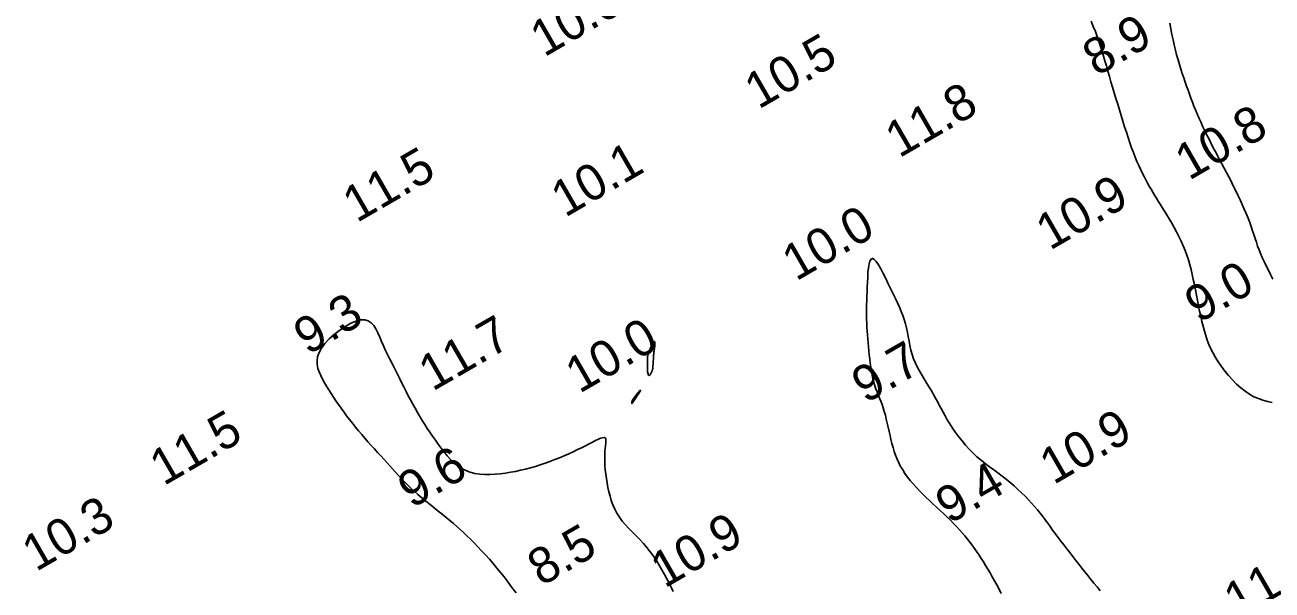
# Model space of a CAD drawing. Extents: x 3024098 to 3056816, y 418252 to 509144.
# Drawn here: x 3035988.1 to 3036161.3, y 419913.7 to 419992.1 of the extents above; entities that cross this region are included whole.
import ezdxf

# ---------------------------------------------------------------- set-up
doc = ezdxf.new("R2010")
doc.units = 0
doc.layers.add('V-CHAN-CONT-EL10', color=7, linetype='Continuous')
doc.layers.add('V-TOPO-SOUN-0911', color=7, linetype='Continuous')

msp = doc.modelspace()

# ---------------------------------------------------------------- linework, layer by layer
at = {"layer": 'V-CHAN-CONT-EL10'}
for points in [[(3036136.16, 419992.61), (3036136.46, 419991.89), (3036136.75, 419991.17), (3036137.01, 419990.48), (3036137.25, 419989.79), (3036137.47, 419989.12), (3036137.69, 419988.45), (3036137.89, 419987.77), (3036138.08, 419987.09), (3036138.28, 419986.4), (3036138.49, 419985.69), (3036138.7, 419984.95), (3036138.92, 419984.2), (3036139.14, 419983.44), (3036139.37, 419982.66), (3036139.61, 419981.87), (3036139.85, 419981.08), (3036140.09, 419980.29), (3036140.33, 419979.51), (3036140.57, 419978.73), (3036140.82, 419977.96), (3036141.06, 419977.2), (3036141.3, 419976.47), (3036141.55, 419975.75), (3036141.79, 419975.06), (3036142.03, 419974.4), (3036142.28, 419973.76), (3036142.52, 419973.16), (3036142.77, 419972.6), (3036143.02, 419972.06), (3036143.26, 419971.55), (3036143.51, 419971.06), (3036143.75, 419970.6), (3036144, 419970.15), (3036144.24, 419969.72), (3036144.48, 419969.3), (3036144.72, 419968.89), (3036144.97, 419968.48), (3036145.22, 419968.07), (3036145.48, 419967.65), (3036145.76, 419967.21), (3036146.04, 419966.74), (3036146.35, 419966.25), (3036146.67, 419965.73), (3036147, 419965.17), (3036147.35, 419964.59), (3036147.69, 419963.99), (3036148.03, 419963.37), (3036148.36, 419962.73), (3036148.67, 419962.09), (3036148.96, 419961.44), (3036149.22, 419960.79), (3036149.45, 419960.14), (3036149.67, 419959.48), (3036149.86, 419958.82), (3036150.04, 419958.14), (3036150.2, 419957.46), (3036150.35, 419956.76), (3036150.5, 419956.05), (3036150.65, 419955.33), (3036150.79, 419954.6), (3036150.93, 419953.85), (3036151.08, 419953.11), (3036151.23, 419952.38), (3036151.38, 419951.66), (3036151.54, 419950.95), (3036151.71, 419950.27), (3036151.89, 419949.61), (3036152.08, 419948.97), (3036152.29, 419948.35), (3036152.53, 419947.74), (3036152.79, 419947.14), (3036153.09, 419946.54), (3036153.43, 419945.93), (3036153.81, 419945.32), (3036154.25, 419944.69), (3036154.72, 419944.06), (3036155.23, 419943.43), (3036155.78, 419942.83), (3036156.35, 419942.25), (3036156.94, 419941.72), (3036157.55, 419941.25), (3036158.16, 419940.84), (3036158.78, 419940.5), (3036159.4, 419940.23), (3036160.03, 419940.02), (3036160.66, 419939.84), (3036161.3, 419939.7)], [(3036161.41, 419956.83), (3036161.09, 419957.47), (3036160.78, 419958.08), (3036160.48, 419958.67), (3036160.2, 419959.25), (3036159.94, 419959.8), (3036159.7, 419960.35), (3036159.48, 419960.88), (3036159.29, 419961.41), (3036159.11, 419961.93), (3036158.94, 419962.46), (3036158.77, 419963), (3036158.59, 419963.54), (3036158.4, 419964.1), (3036158.19, 419964.68), (3036157.96, 419965.28), (3036157.71, 419965.91), (3036157.44, 419966.54), (3036157.15, 419967.19), (3036156.85, 419967.84), (3036156.54, 419968.49), (3036156.22, 419969.14), (3036155.9, 419969.78), (3036155.59, 419970.41), (3036155.27, 419971.02), (3036154.95, 419971.62), (3036154.63, 419972.22), (3036154.32, 419972.81), (3036154.01, 419973.39), (3036153.7, 419973.98), (3036153.39, 419974.56), (3036153.08, 419975.15), (3036152.78, 419975.73), (3036152.49, 419976.32), (3036152.2, 419976.91), (3036151.92, 419977.49), (3036151.65, 419978.06), (3036151.39, 419978.63), (3036151.13, 419979.2), (3036150.9, 419979.75), (3036150.67, 419980.3), (3036150.45, 419980.84), (3036150.23, 419981.38), (3036150.03, 419981.92), (3036149.83, 419982.47), (3036149.62, 419983.03), (3036149.42, 419983.59), (3036149.22, 419984.17), (3036149.02, 419984.76), (3036148.81, 419985.36), (3036148.62, 419985.97), (3036148.42, 419986.61), (3036148.23, 419987.26), (3036148.04, 419987.93), (3036147.87, 419988.61), (3036147.7, 419989.32), (3036147.54, 419990.05), (3036147.39, 419990.79), (3036147.24, 419991.55), (3036147.09, 419992.33)], [(3036137.44, 419913.57), (3036136.99, 419914.09), (3036136.55, 419914.62), (3036136.12, 419915.14), (3036135.71, 419915.66), (3036135.29, 419916.19), (3036134.88, 419916.72), (3036134.47, 419917.25), (3036134.05, 419917.78), (3036133.63, 419918.32), (3036133.2, 419918.86), (3036132.78, 419919.4), (3036132.37, 419919.94), (3036131.96, 419920.46), (3036131.56, 419920.98), (3036131.18, 419921.49), (3036130.82, 419921.98), (3036130.47, 419922.46), (3036130.13, 419922.93), (3036129.79, 419923.39), (3036129.44, 419923.85), (3036129.08, 419924.31), (3036128.71, 419924.78), (3036128.32, 419925.24), (3036127.9, 419925.72), (3036127.46, 419926.2), (3036126.99, 419926.68), (3036126.5, 419927.16), (3036126, 419927.64), (3036125.47, 419928.11), (3036124.93, 419928.58), (3036124.37, 419929.03), (3036123.79, 419929.47), (3036123.21, 419929.91), (3036122.63, 419930.34), (3036122.04, 419930.77), (3036121.46, 419931.21), (3036120.88, 419931.67), (3036120.31, 419932.15), (3036119.76, 419932.66), (3036119.23, 419933.2), (3036118.71, 419933.77), (3036118.23, 419934.35), (3036117.76, 419934.95), (3036117.33, 419935.54), (3036116.92, 419936.14), (3036116.54, 419936.72), (3036116.19, 419937.29), (3036115.88, 419937.83), (3036115.59, 419938.35), (3036115.33, 419938.85), (3036115.07, 419939.34), (3036114.81, 419939.83), (3036114.56, 419940.31), (3036114.29, 419940.8), (3036114, 419941.3), (3036113.69, 419941.81), (3036113.36, 419942.34), (3036113.02, 419942.88), (3036112.68, 419943.43), (3036112.35, 419943.99), (3036112.04, 419944.57), (3036111.75, 419945.16), (3036111.5, 419945.75), (3036111.3, 419946.36), (3036111.13, 419946.97), (3036110.99, 419947.59), (3036110.87, 419948.21), (3036110.75, 419948.83), (3036110.64, 419949.43), (3036110.51, 419950.04), (3036110.37, 419950.63), (3036110.2, 419951.2), (3036110, 419951.77), (3036109.78, 419952.34), (3036109.53, 419952.92), (3036109.26, 419953.51), (3036108.97, 419954.12), (3036108.66, 419954.76), (3036108.33, 419955.44), (3036107.99, 419956.15), (3036107.64, 419956.88), (3036107.29, 419957.59), (3036106.94, 419958.24), (3036106.61, 419958.8), (3036106.3, 419959.26), (3036106.03, 419959.56), (3036105.79, 419959.68), (3036105.6, 419959.6), (3036105.44, 419959.33), (3036105.33, 419958.92), (3036105.24, 419958.39), (3036105.17, 419957.77), (3036105.13, 419957.1), (3036105.09, 419956.4), (3036105.06, 419955.72), (3036105.04, 419955.07), (3036105.02, 419954.45), (3036105, 419953.86), (3036104.98, 419953.3), (3036104.97, 419952.76), (3036104.96, 419952.23), (3036104.96, 419951.71), (3036104.97, 419951.19), (3036104.99, 419950.67), (3036105.02, 419950.14), (3036105.05, 419949.61), (3036105.09, 419949.07), (3036105.13, 419948.53), (3036105.18, 419947.98), (3036105.23, 419947.42), (3036105.29, 419946.86), (3036105.35, 419946.29), (3036105.41, 419945.72), (3036105.48, 419945.15), (3036105.56, 419944.59), (3036105.65, 419944.04), (3036105.75, 419943.5), (3036105.86, 419942.98), (3036105.98, 419942.49), (3036106.12, 419942.02), (3036106.28, 419941.58), (3036106.45, 419941.15), (3036106.62, 419940.72), (3036106.79, 419940.3), (3036106.96, 419939.86), (3036107.13, 419939.42), (3036107.29, 419938.95), (3036107.44, 419938.45), (3036107.58, 419937.92), (3036107.71, 419937.38), (3036107.84, 419936.82), (3036107.97, 419936.25), (3036108.1, 419935.68), (3036108.23, 419935.1), (3036108.36, 419934.54), (3036108.5, 419933.98), (3036108.66, 419933.43), (3036108.82, 419932.9), (3036109.01, 419932.37), (3036109.21, 419931.85), (3036109.45, 419931.34), (3036109.7, 419930.83), (3036109.99, 419930.33), (3036110.31, 419929.84), (3036110.67, 419929.35), (3036111.05, 419928.87), (3036111.45, 419928.39), (3036111.88, 419927.92), (3036112.33, 419927.45), (3036112.79, 419926.98), (3036113.26, 419926.52), (3036113.74, 419926.06), (3036114.23, 419925.6), (3036114.72, 419925.14), (3036115.21, 419924.69), (3036115.69, 419924.24), (3036116.16, 419923.79), (3036116.62, 419923.35), (3036117.06, 419922.91), (3036117.48, 419922.47), (3036117.88, 419922.04), (3036118.27, 419921.6), (3036118.63, 419921.17), (3036118.99, 419920.74), (3036119.33, 419920.31), (3036119.66, 419919.87), (3036119.98, 419919.42), (3036120.29, 419918.97), (3036120.6, 419918.52), (3036120.9, 419918.05), (3036121.21, 419917.57), (3036121.51, 419917.08), (3036121.81, 419916.57), (3036122.12, 419916.05), (3036122.43, 419915.51), (3036122.74, 419914.96), (3036123.06, 419914.38), (3036123.37, 419913.78), (3036123.69, 419913.16)], [(3036078.12, 419913.48), (3036077.84, 419914.04), (3036077.54, 419914.62), (3036077.23, 419915.23), (3036076.9, 419915.84), (3036076.55, 419916.48), (3036076.18, 419917.11), (3036075.79, 419917.74), (3036075.37, 419918.37), (3036074.93, 419918.98), (3036074.47, 419919.56), (3036073.98, 419920.12), (3036073.48, 419920.66), (3036072.96, 419921.19), (3036072.46, 419921.7), (3036071.96, 419922.21), (3036071.49, 419922.72), (3036071.05, 419923.24), (3036070.65, 419923.77), (3036070.3, 419924.32), (3036070, 419924.89), (3036069.74, 419925.48), (3036069.52, 419926.08), (3036069.34, 419926.68), (3036069.18, 419927.3), (3036069.05, 419927.91), (3036068.94, 419928.53), (3036068.84, 419929.14), (3036068.76, 419929.74), (3036068.69, 419930.33), (3036068.64, 419930.9), (3036068.61, 419931.45), (3036068.6, 419931.97), (3036068.6, 419932.46), (3036068.62, 419932.92), (3036068.66, 419933.33), (3036068.7, 419933.7), (3036068.74, 419934.03), (3036068.77, 419934.3), (3036068.77, 419934.53), (3036068.74, 419934.69), (3036068.66, 419934.79), (3036068.52, 419934.84), (3036068.31, 419934.81), (3036068.04, 419934.73), (3036067.72, 419934.59), (3036067.33, 419934.42), (3036066.91, 419934.2), (3036066.43, 419933.96), (3036065.92, 419933.7), (3036065.38, 419933.42), (3036064.81, 419933.15), (3036064.22, 419932.86), (3036063.6, 419932.58), (3036062.97, 419932.3), (3036062.32, 419932.03), (3036061.66, 419931.76), (3036061, 419931.5), (3036060.32, 419931.26), (3036059.65, 419931.03), (3036058.97, 419930.82), (3036058.29, 419930.62), (3036057.61, 419930.44), (3036056.92, 419930.28), (3036056.22, 419930.13), (3036055.52, 419930), (3036054.81, 419929.89), (3036054.09, 419929.8), (3036053.37, 419929.73), (3036052.65, 419929.7), (3036051.94, 419929.7), (3036051.25, 419929.75), (3036050.57, 419929.85), (3036049.93, 419930.02), (3036049.31, 419930.24), (3036048.74, 419930.55), (3036048.19, 419930.91), (3036047.68, 419931.33), (3036047.2, 419931.8), (3036046.74, 419932.3), (3036046.3, 419932.83), (3036045.88, 419933.37), (3036045.48, 419933.92), (3036045.08, 419934.47), (3036044.69, 419935.01), (3036044.32, 419935.56), (3036043.95, 419936.1), (3036043.6, 419936.65), (3036043.25, 419937.2), (3036042.91, 419937.76), (3036042.58, 419938.32), (3036042.26, 419938.89), (3036041.94, 419939.46), (3036041.63, 419940.05), (3036041.32, 419940.64), (3036041.01, 419941.24), (3036040.71, 419941.85), (3036040.4, 419942.46), (3036040.08, 419943.08), (3036039.76, 419943.71), (3036039.44, 419944.35), (3036039.12, 419944.99), (3036038.8, 419945.63), (3036038.49, 419946.27), (3036038.18, 419946.9), (3036037.89, 419947.54), (3036037.61, 419948.16), (3036037.35, 419948.78), (3036037.09, 419949.36), (3036036.82, 419949.9), (3036036.52, 419950.37), (3036036.18, 419950.75), (3036035.77, 419951.02), (3036035.3, 419951.17), (3036034.74, 419951.16), (3036034.08, 419951), (3036033.35, 419950.69), (3036032.58, 419950.26), (3036031.8, 419949.74), (3036031.05, 419949.15), (3036030.35, 419948.52), (3036029.75, 419947.88), (3036029.27, 419947.24), (3036028.93, 419946.63), (3036028.73, 419946.04), (3036028.65, 419945.49), (3036028.67, 419944.95), (3036028.77, 419944.43), (3036028.94, 419943.93), (3036029.16, 419943.43), (3036029.42, 419942.93), (3036029.69, 419942.43), (3036029.98, 419941.94), (3036030.28, 419941.44), (3036030.59, 419940.94), (3036030.92, 419940.43), (3036031.27, 419939.93), (3036031.62, 419939.42), (3036031.99, 419938.9), (3036032.37, 419938.38), (3036032.76, 419937.86), (3036033.16, 419937.34), (3036033.57, 419936.81), (3036033.99, 419936.29), (3036034.42, 419935.77), (3036034.85, 419935.25), (3036035.28, 419934.74), (3036035.72, 419934.23), (3036036.17, 419933.74), (3036036.61, 419933.25), (3036037.05, 419932.76), (3036037.49, 419932.29), (3036037.92, 419931.82), (3036038.34, 419931.36), (3036038.76, 419930.9), (3036039.16, 419930.45), (3036039.56, 419930.01), (3036039.96, 419929.57), (3036040.36, 419929.14), (3036040.78, 419928.7), (3036041.21, 419928.26), (3036041.67, 419927.82), (3036042.15, 419927.37), (3036042.67, 419926.92), (3036043.21, 419926.46), (3036043.77, 419926), (3036044.34, 419925.54), (3036044.91, 419925.09), (3036045.48, 419924.63), (3036046.04, 419924.19), (3036046.58, 419923.75), (3036047.09, 419923.33), (3036047.58, 419922.91), (3036048.06, 419922.49), (3036048.53, 419922.07), (3036049, 419921.64), (3036049.47, 419921.18), (3036049.95, 419920.71), (3036050.45, 419920.21), (3036050.96, 419919.68), (3036051.5, 419919.11), (3036052.04, 419918.53), (3036052.58, 419917.93), (3036053.11, 419917.33), (3036053.64, 419916.72), (3036054.14, 419916.11), (3036054.62, 419915.51), (3036055.07, 419914.92), (3036055.49, 419914.35), (3036055.9, 419913.8), (3036056.29, 419913.27)]]:
    msp.add_lwpolyline(points, dxfattribs=at)
for points in [[(3036075.16, 419944.05), (3036075.19, 419944.11), (3036075.21, 419944.16), (3036075.23, 419944.22), (3036075.25, 419944.29), (3036075.27, 419944.38), (3036075.28, 419944.49), (3036075.3, 419944.63), (3036075.31, 419944.79), (3036075.33, 419944.99), (3036075.34, 419945.2), (3036075.35, 419945.42), (3036075.36, 419945.64), (3036075.37, 419945.86), (3036075.38, 419946.06), (3036075.4, 419946.24), (3036075.41, 419946.39), (3036075.42, 419946.52), (3036075.43, 419946.64), (3036075.44, 419946.74), (3036075.46, 419946.84), (3036075.47, 419946.95), (3036075.49, 419947.07), (3036075.51, 419947.2), (3036075.53, 419947.35), (3036075.55, 419947.52), (3036075.57, 419947.69), (3036075.58, 419947.85), (3036075.58, 419947.99), (3036075.57, 419948.09), (3036075.54, 419948.15), (3036075.5, 419948.16), (3036075.43, 419948.1), (3036075.35, 419947.98), (3036075.25, 419947.82), (3036075.15, 419947.63), (3036075.04, 419947.42), (3036074.94, 419947.2), (3036074.85, 419946.98), (3036074.76, 419946.79), (3036074.7, 419946.61), (3036074.65, 419946.46), (3036074.61, 419946.32), (3036074.59, 419946.19), (3036074.57, 419946.06), (3036074.56, 419945.93), (3036074.55, 419945.79), (3036074.55, 419945.64), (3036074.54, 419945.47), (3036074.54, 419945.29), (3036074.54, 419945.09), (3036074.53, 419944.89), (3036074.54, 419944.68), (3036074.54, 419944.48), (3036074.55, 419944.29), (3036074.56, 419944.11), (3036074.57, 419943.94), (3036074.6, 419943.8), (3036074.62, 419943.67), (3036074.65, 419943.57), (3036074.68, 419943.49), (3036074.72, 419943.44), (3036074.76, 419943.41), (3036074.8, 419943.41), (3036074.84, 419943.44), (3036074.88, 419943.49), (3036074.93, 419943.55), (3036074.97, 419943.64), (3036075.01, 419943.72), (3036075.06, 419943.82), (3036075.09, 419943.9), (3036075.13, 419943.98)], [(3036072.95, 419940.39), (3036073.08, 419940.58), (3036073.21, 419940.77), (3036073.33, 419940.96), (3036073.44, 419941.12), (3036073.52, 419941.26), (3036073.57, 419941.35), (3036073.58, 419941.39), (3036073.54, 419941.37), (3036073.45, 419941.29), (3036073.34, 419941.18), (3036073.2, 419941.03), (3036073.06, 419940.85), (3036072.91, 419940.67), (3036072.77, 419940.48), (3036072.64, 419940.3), (3036072.54, 419940.14), (3036072.47, 419940), (3036072.42, 419939.87), (3036072.38, 419939.77), (3036072.37, 419939.68), (3036072.36, 419939.62), (3036072.37, 419939.58), (3036072.39, 419939.55), (3036072.41, 419939.56), (3036072.43, 419939.58), (3036072.47, 419939.63), (3036072.52, 419939.7), (3036072.57, 419939.79), (3036072.64, 419939.91), (3036072.73, 419940.04), (3036072.83, 419940.21)]]:
    msp.add_lwpolyline(points, close=True, dxfattribs=at)

# ---------------------------------------------------------------- texts
at = {"layer": 'V-TOPO-SOUN-0911'}
for s, p in [('10.0 ', (3036060.2, 419987.57)), ('8.9', (3036136.92, 419984.89)), ('10.5 ', (3036089.97, 419980.32)), ('11.8 ', (3036109.5, 419973.56)), ('10.8 ', (3036149.75, 419970.44)), ('11.5 ', (3036034.16, 419964.57)), ('10.1 ', (3036063.09, 419965.31)), ('10.9 ', (3036130.43, 419960.73)), ('10.0 ', (3036095.18, 419956.47)), ('9.0', (3036151.11, 419950.63)), ('9.3', (3036027.34, 419946.21)), ('11.7 ', (3036044.7, 419941.18)), ('10.0 ', (3036065.09, 419940.88)), ('9.7', (3036104.84, 419939.48)), ('11.5 ', (3036007.35, 419928.06)), ('10.9 ', (3036130.95, 419928.22)), ('9.6', (3036041.81, 419924.92)), ('9.4', (3036116.48, 419922.75)), ('10.3 ', (3035989.62, 419916.15)), ('10.9 ', (3036076.92, 419913.85)), ('8.5', (3036059.81, 419914.12)), ('11.0 ', (3036156.53, 419909.58))]:
    msp.add_text(s, height=5, rotation=30, dxfattribs=at).set_placement(p)

doc.saveas('drawing.dxf')
